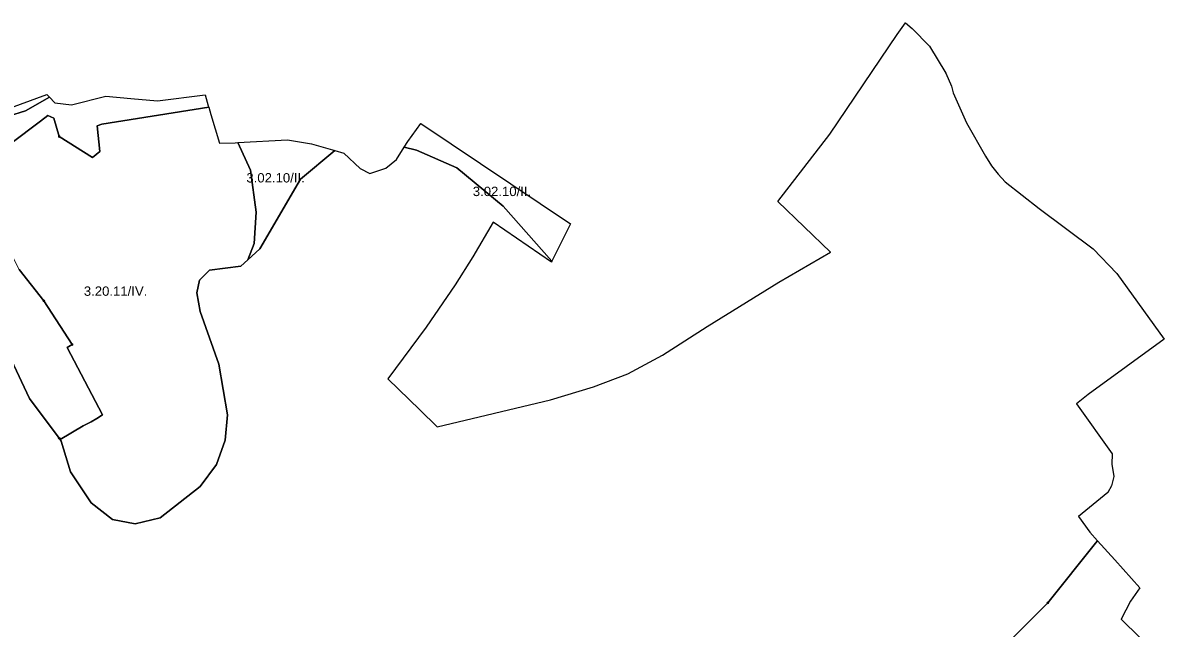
# Model space of a CAD drawing. Extents: x -650455 to -642254, y -1075222 to -1066610.
# Drawn here: x -643766 to -642546, y -1069652 to -1069006 of the extents above; entities that cross this region are included whole.
import ezdxf
from ezdxf.enums import TextEntityAlignment as Align

# ---------------------------------------------------------------- set-up
doc = ezdxf.new("R2010")
doc.units = 0
doc.header["$LTSCALE"] = 4
doc.header["$PDMODE"] = 32
doc.header["$PDSIZE"] = 2
for name, color, linetype, lineweight in [('1', 7, 'Continuous', 25), ('11', 7, 'Continuous', 13), ('12', 7, 'Continuous', 13), ('14', 7, 'Continuous', 13)]:
    doc.layers.add(name, color=color, linetype=linetype, lineweight=lineweight)
doc.layers.add('2', color=7, linetype='Continuous')

msp = doc.modelspace()

# ---------------------------------------------------------------- linework, layer by layer
at = {"layer": '1'}
for points in [[(-643253, -1069201.5), (-643200.685, -1069260.355), (-643201.204, -1069261.41), (-643263.608, -1069218.549), (-643285.341, -1069255.509), (-643304.279, -1069285.638), (-643335.326, -1069330.673), (-643376.308, -1069385.959), (-643342.157, -1069419.193), (-643323.529, -1069437.207), (-643202.136, -1069408.632), (-643156.187, -1069394.655), (-643119.552, -1069380.678), (-643082.606, -1069360.801), (-643034.794, -1069330.052), (-642958.109, -1069282.531), (-642902.846, -1069250.54), (-642959.282, -1069196.43), (-642903.444, -1069124.462), (-642831.547, -1069017.823), (-642822.603, -1069005.526), (-642815.422, -1069011.749), (-642797.105, -1069030.384), (-642779.422, -1069059.24), (-642773.657, -1069073.076), (-642771.588, -1069080.346), (-642757.371, -1069112.568), (-642737.193, -1069148.167), (-642730.707, -1069158.4), (-642723.789, -1069167.336), (-642716.252, -1069175.573), (-642679.927, -1069203.837), (-642622.18, -1069247.009), (-642596.722, -1069273.41), (-642546.116, -1069343.605), (-642627.309, -1069402.672), (-642639.728, -1069412.612), (-642601.851, -1069466.034), (-642602.161, -1069477.215), (-642599.988, -1069490.572)], [(-643800.5, -1069111.001), (-643763.5, -1069099.501), (-643738.043, -1069084.954), (-643732.105, -1069090.895), (-643714.408, -1069093.068), (-643677.773, -1069084.062), (-643650.919, -1069086.417), (-643622.509, -1069088.72), (-643571.628, -1069082.364), (-643568.168, -1069094.094), (-643567.686, -1069095.727), (-643682, -1069114), (-643687, -1069115.501), (-643684, -1069143.001), (-643692, -1069149.5), (-643727.5, -1069127.001), (-643733.5, -1069107.501), (-643739.66, -1069104.58), (-643747.75, -1069110.71), (-643779.31, -1069134.631)], [(-643779.31, -1069134.631), (-643747.75, -1069110.71), (-643739.66, -1069104.58), (-643733.5, -1069107.501), (-643727.5, -1069127.001), (-643692, -1069149.5), (-643684, -1069143.001)], [(-643684, -1069143.001), (-643687, -1069115.501), (-643682, -1069114), (-643567.686, -1069095.727), (-643565.388, -1069103.519), (-643556.379, -1069134.068), (-643539.614, -1069133.757), (-643536.575, -1069133.589)], [(-643779, -1069365.501), (-643759.5, -1069407.001), (-643727.662, -1069449.608), (-643726.74, -1069450.721), (-643725.5, -1069452.5), (-643715.5, -1069485.5), (-643693.5, -1069518.5), (-643670.5, -1069536.501), (-643646.5, -1069541.001), (-643619.5, -1069534.5), (-643577, -1069501), (-643559.5, -1069477.5), (-643550, -1069451.501), (-643547.5, -1069424.5), (-643557, -1069370.501), (-643577, -1069314.001), (-643580.5, -1069294.001), (-643577.5, -1069280.501), (-643567, -1069270.001), (-643533.5, -1069265.501), (-643526, -1069259), (-643513, -1069247), (-643469.5, -1069172.501), (-643432.983, -1069142.138), (-643423.189, -1069144.938), (-643405.803, -1069161.088), (-643395.557, -1069166.679), (-643378.481, -1069160.778), (-643366.994, -1069151.459), (-643358.703, -1069138.487), (-643345.5, -1069141.5), (-643302.5, -1069160.501), (-643253, -1069201.5)], [(-643536.575, -1069133.589), (-643523, -1069163.001), (-643517, -1069208.001), (-643519, -1069241.501), (-643526, -1069259), (-643533.5, -1069265.501), (-643567, -1069270.001), (-643577.5, -1069280.501), (-643580.5, -1069294.001), (-643577, -1069314.001), (-643557, -1069370.501), (-643547.5, -1069424.5), (-643550, -1069451.501), (-643559.5, -1069477.5), (-643577, -1069501), (-643619.5, -1069534.5), (-643646.5, -1069541.001), (-643670.5, -1069536.501), (-643693.5, -1069518.5), (-643715.5, -1069485.5), (-643725.5, -1069452.5), (-643726.74, -1069450.721), (-643701.88, -1069436.351), (-643693.28, -1069431.83), (-643687.502, -1069428.356), (-643681.472, -1069424.524), (-643719.17, -1069352.441), (-643713.86, -1069349.23), (-643744, -1069302.5), (-643770.5, -1069269.001)], [(-643770.5, -1069269.001), (-643744, -1069302.5), (-643713.86, -1069349.23)], [(-643713.86, -1069349.23), (-643719.17, -1069352.441), (-643681.472, -1069424.524), (-643687.502, -1069428.356), (-643693.28, -1069431.83), (-643701.88, -1069436.351), (-643726.74, -1069450.721), (-643727.662, -1069449.608), (-643759.5, -1069407.001), (-643779, -1069365.501)], [(-642599.988, -1069490.572), (-642602.471, -1069500.2), (-642606.508, -1069507.654), (-642637.554, -1069533.122), (-642625.757, -1069549.894), (-642617.261, -1069559.279)], [(-642617.261, -1069559.279), (-642619.5, -1069561.501), (-642670.5, -1069625.501), (-642716, -1069671)], [(-642716, -1069671), (-642670.5, -1069625.501), (-642619.5, -1069561.501), (-642617.261, -1069559.279), (-642599.044, -1069579.399), (-642572.046, -1069609.218), (-642581.981, -1069623.817), (-642592.226, -1069642.762), (-642552.355, -1069682.197)]]:
    msp.add_lwpolyline(points, dxfattribs=at)
for points in [[(-643800.5, -1069111.001), (-643835.5, -1069116.001), (-643842.005, -1069115.738), (-643825.555, -1069113.258), (-643740.798, -1069082.197), (-643738.043, -1069084.954), (-643763.5, -1069099.501)], [(-643181.023, -1069220.412), (-643200.685, -1069260.355), (-643253, -1069201.5), (-643302.5, -1069160.501), (-643345.5, -1069141.5), (-643358.703, -1069138.487), (-643354.885, -1069132.514), (-643340.914, -1069113.257)], [(-643513, -1069247), (-643526, -1069259), (-643519, -1069241.501), (-643517, -1069208.001), (-643523, -1069163.001), (-643536.575, -1069133.589), (-643483.419, -1069130.65), (-643457.961, -1069134.998), (-643432.983, -1069142.138), (-643469.5, -1069172.501)]]:
    msp.add_lwpolyline(points, close=True, dxfattribs=at)
at = {"layer": '11'}
for points in [[(-642670.5, -1069625.501), (-642619.5, -1069561.501), (-642617.261, -1069559.279), (-642625.757, -1069549.894), (-642637.554, -1069533.122), (-642606.508, -1069507.654), (-642602.471, -1069500.2), (-642599.988, -1069490.572), (-642602.161, -1069477.215), (-642601.851, -1069466.034), (-642639.728, -1069412.612), (-642627.309, -1069402.672), (-642546.116, -1069343.605), (-642596.722, -1069273.41), (-642622.18, -1069247.009), (-642679.927, -1069203.837), (-642716.252, -1069175.573), (-642723.789, -1069167.336), (-642730.707, -1069158.4), (-642737.193, -1069148.167), (-642757.371, -1069112.568), (-642771.588, -1069080.346), (-642773.657, -1069073.076), (-642779.422, -1069059.24), (-642797.105, -1069030.384), (-642815.422, -1069011.749), (-642822.603, -1069005.526), (-642831.547, -1069017.823), (-642903.444, -1069124.462), (-642959.282, -1069196.43), (-642902.846, -1069250.54), (-642958.109, -1069282.531), (-643034.794, -1069330.052), (-643082.606, -1069360.801), (-643119.552, -1069380.678), (-643156.187, -1069394.655), (-643202.136, -1069408.632), (-643323.529, -1069437.207), (-643342.157, -1069419.193), (-643376.308, -1069385.959)], [(-643376.308, -1069385.959), (-643335.326, -1069330.673), (-643304.279, -1069285.638), (-643285.341, -1069255.509), (-643263.608, -1069218.549), (-643201.204, -1069261.41), (-643200.685, -1069260.355), (-643253, -1069201.5), (-643302.5, -1069160.501), (-643345.5, -1069141.5), (-643358.703, -1069138.487), (-643366.994, -1069151.459), (-643378.481, -1069160.778), (-643395.557, -1069166.679), (-643405.803, -1069161.088), (-643423.189, -1069144.938), (-643432.983, -1069142.138), (-643469.5, -1069172.501), (-643513, -1069247), (-643526, -1069259), (-643533.5, -1069265.501), (-643567, -1069270.001), (-643577.5, -1069280.501), (-643580.5, -1069294.001), (-643577, -1069314.001), (-643557, -1069370.501), (-643547.5, -1069424.5), (-643550, -1069451.501), (-643559.5, -1069477.5), (-643577, -1069501), (-643619.5, -1069534.5), (-643646.5, -1069541.001), (-643670.5, -1069536.501), (-643693.5, -1069518.5), (-643715.5, -1069485.5), (-643725.5, -1069452.5), (-643726.74, -1069450.721), (-643727.662, -1069449.608)], [(-643727.662, -1069449.608), (-643759.5, -1069407.001), (-643779, -1069365.501)], [(-642719.154, -1069675.872), (-642716, -1069671), (-642670.5, -1069625.501)]]:
    msp.add_lwpolyline(points, dxfattribs=at)
for p in [(-643727.662, -1069449.608), (-642670.5, -1069625.501)]:
    msp.add_point(p, dxfattribs=at)
at = {"layer": '12'}
for points in [[(-643200.685, -1069260.355), (-643181.023, -1069220.412), (-643340.914, -1069113.257), (-643354.885, -1069132.514), (-643358.703, -1069138.487), (-643345.5, -1069141.5), (-643302.5, -1069160.501), (-643253, -1069201.5)], [(-643519, -1069241.501), (-643526, -1069259), (-643513, -1069247), (-643469.5, -1069172.501), (-643432.983, -1069142.138), (-643457.961, -1069134.998), (-643483.419, -1069130.65), (-643536.575, -1069133.589), (-643523, -1069163.001), (-643517, -1069208.001)]]:
    msp.add_lwpolyline(points, close=True, dxfattribs=at)
msp.add_lwpolyline([(-642577, -1069806), (-642571, -1069755.001), (-642552.355, -1069682.197), (-642592.226, -1069642.762), (-642581.981, -1069623.817), (-642572.046, -1069609.218), (-642599.044, -1069579.399), (-642617.261, -1069559.279), (-642619.5, -1069561.501), (-642670.5, -1069625.501), (-642716, -1069671)], dxfattribs=at)
at = {"layer": '14'}
msp.add_line((-643744, -1069302.5), (-643713.86, -1069349.23), dxfattribs=at)
for points in [[(-643727.5, -1069127.001), (-643733.5, -1069107.501), (-643739.66, -1069104.58), (-643747.75, -1069110.71), (-643779.31, -1069134.631), (-643792.04, -1069142.271), (-643799.5, -1069189.001), (-643786.5, -1069237.501), (-643770.5, -1069269.001), (-643744, -1069302.5)], [(-643681.472, -1069424.524), (-643687.502, -1069428.356), (-643693.28, -1069431.83), (-643701.88, -1069436.351), (-643726.74, -1069450.721), (-643725.5, -1069452.5), (-643715.5, -1069485.5), (-643693.5, -1069518.5), (-643670.5, -1069536.501), (-643646.5, -1069541.001), (-643619.5, -1069534.5), (-643577, -1069501), (-643559.5, -1069477.5), (-643550, -1069451.501), (-643547.5, -1069424.5), (-643557, -1069370.501), (-643577, -1069314.001), (-643580.5, -1069294.001), (-643577.5, -1069280.501), (-643567, -1069270.001), (-643533.5, -1069265.501), (-643526, -1069259), (-643519, -1069241.501), (-643517, -1069208.001), (-643523, -1069163.001), (-643536.575, -1069133.589), (-643539.614, -1069133.757), (-643556.379, -1069134.068), (-643565.388, -1069103.519), (-643567.686, -1069095.727), (-643682, -1069114), (-643687, -1069115.501), (-643684, -1069143.001), (-643692, -1069149.5), (-643727.5, -1069127.001)], [(-643713.86, -1069349.23), (-643719.17, -1069352.441), (-643681.472, -1069424.524)]]:
    msp.add_lwpolyline(points, dxfattribs=at)
for p in [(-643727.5, -1069127.001), (-643744, -1069302.5), (-643713.86, -1069349.23)]:
    msp.add_point(p, dxfattribs=at)

# ---------------------------------------------------------------- texts
at = {"layer": '2', "width": 1.05}
for s, p in [('3.02.10/II.', (-643496.256, -1069176.155)), ('3.02.10/II.', (-643254.154, -1069190.685)), ('3.20.11/IV.', (-643667.326, -1069297.283))]:
    msp.add_text(s, height=10, dxfattribs=at).set_placement(p, align=Align.CENTER)

doc.saveas('drawing.dxf')
